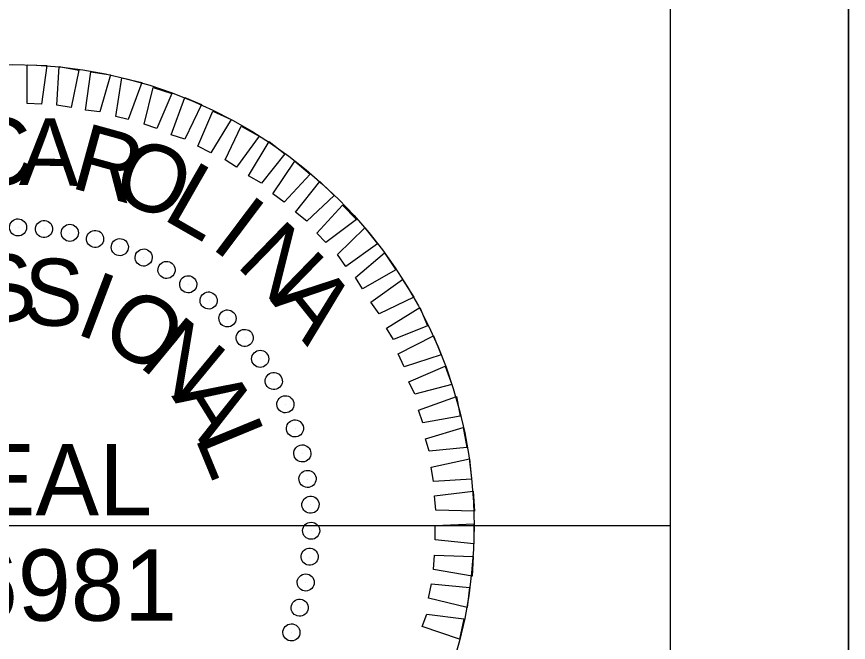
# Model space of a CAD drawing. Extents: x 1184121 to 1184397, y 1246506 to 1246661.
# Drawn here: x 1184351.43 to 1184360.32, y 1246631.37 to 1246638.07 of the extents above; entities that cross this region are included whole.
import ezdxf

# ---------------------------------------------------------------- set-up
doc = ezdxf.new("R2010")
doc.units = 0
for name, color, linetype in [('Scratch_Level_3', 7, 'Continuous'), ('Sheet PE Seal Cell', 7, 'Continuous'), ('Sheet Plan CELL', 7, 'Continuous'), ('Sheet Plot Border Outside CELL', 7, 'Continuous'), ('z - Construction', 7, 'Continuous')]:
    doc.layers.add(name, color=color, linetype=linetype)

msp = doc.modelspace()

# ---------------------------------------------------------------- linework, layer by layer
at = {"layer": 'Scratch_Level_3'}
msp.add_line((1184358.4219, 1246632.6201), (1184344.3472, 1246632.6204), dxfattribs=at)
msp.add_circle((1184351.3846, 1246632.6203), 4.9351, dxfattribs=at)
at = {"layer": 'Sheet PE Seal Cell'}
for p, q in [((1184351.4441, 1246635.8158), (1184351.4441, 1246635.8158)), ((1184351.724, 1246635.7967), (1184351.724, 1246635.7967)), ((1184351.9976, 1246635.7521), (1184351.9976, 1246635.7521)), ((1184352.2648, 1246635.6949), (1184352.2648, 1246635.6949)), ((1184352.532, 1246635.6058), (1184352.532, 1246635.6058)), ((1184352.7865, 1246635.4913), (1184352.7865, 1246635.4913)), ((1184353.0346, 1246635.3641), (1184353.0346, 1246635.3641)), ((1184353.2636, 1246635.205), (1184353.2636, 1246635.205)), ((1184353.4863, 1246635.0332), (1184353.4863, 1246635.0332)), ((1184353.6835, 1246634.8424), (1184353.6835, 1246634.8424)), ((1184353.8744, 1246634.6324), (1184353.8744, 1246634.6324)), ((1184354.0334, 1246634.4098), (1184354.0334, 1246634.4098)), ((1184354.1797, 1246634.168), (1184354.1797, 1246634.168)), ((1184354.307, 1246633.9199), (1184354.307, 1246633.9199)), ((1184354.4088, 1246633.6654), (1184354.4088, 1246633.6654)), ((1184354.4851, 1246633.3982), (1184354.4851, 1246633.3982)), ((1184354.536, 1246633.1183), (1184354.536, 1246633.1183)), ((1184354.5742, 1246632.8447), (1184354.5742, 1246632.8447)), ((1184354.5805, 1246632.5648), (1184354.5805, 1246632.5648)), ((1184354.5615, 1246632.2849), (1184354.5615, 1246632.2849)), ((1184354.5169, 1246632.0113), (1184354.5169, 1246632.0113)), ((1184354.4597, 1246631.7441), (1184354.4597, 1246631.7441)), ((1184354.3706, 1246631.4769), (1184354.3706, 1246631.4769))]:
    msp.add_line(p, q, dxfattribs=at)
for points in [[(1184351.5395, 1246637.1391), (1184351.5395, 1246637.5526), (1184351.7495, 1246637.5462), (1184351.6922, 1246637.1327)], [(1184351.8576, 1246637.12), (1184351.8831, 1246637.5335), (1184352.093, 1246637.4953), (1184352.0103, 1246637.0945)], [(1184352.163, 1246637.0691), (1184352.2202, 1246637.4762), (1184352.4302, 1246637.4444), (1184352.3157, 1246637.05)], [(1184352.4874, 1246636.9991), (1184352.5511, 1246637.4126), (1184352.7674, 1246637.3617), (1184352.621, 1246636.9673)], [(1184352.7928, 1246636.9164), (1184352.8883, 1246637.3108), (1184353.0855, 1246637.2472), (1184352.9264, 1246636.8719)], [(1184353.0791, 1246636.8019), (1184353.2254, 1246637.2027), (1184353.4036, 1246637.1263), (1184353.2254, 1246636.7573)], [(1184353.3654, 1246636.681), (1184353.5245, 1246637.0564), (1184353.7217, 1246636.9673), (1184353.5054, 1246636.611)], [(1184353.6581, 1246636.5347), (1184353.8298, 1246636.8973), (1184354.0207, 1246636.7891), (1184353.7789, 1246636.4583)], [(1184353.9062, 1246636.3629), (1184354.1288, 1246636.7319), (1184354.2943, 1246636.5983), (1184354.0461, 1246636.2866)], [(1184354.167, 1246636.172), (1184354.4024, 1246636.5219), (1184354.5678, 1246636.382), (1184354.2879, 1246636.083)], [(1184354.4088, 1246635.9748), (1184354.6696, 1246636.3056), (1184354.8223, 1246636.1529), (1184354.5296, 1246635.8794)], [(1184354.6378, 1246635.7521), (1184354.9114, 1246636.0512), (1184355.0641, 1246635.8985), (1184354.7332, 1246635.6504)], [(1184354.8605, 1246635.5231), (1184355.1531, 1246635.8094), (1184355.2867, 1246635.6376), (1184354.9495, 1246635.3959)], [(1184355.0513, 1246635.275), (1184355.3631, 1246635.5422), (1184355.4839, 1246635.3577), (1184355.1277, 1246635.1541)], [(1184355.2167, 1246635.0142), (1184355.5539, 1246635.2559), (1184355.6748, 1246635.065), (1184355.3058, 1246634.8869)], [(1184355.3822, 1246634.7342), (1184355.7384, 1246634.9569), (1184355.8211, 1246634.7597), (1184355.4585, 1246634.6133)], [(1184355.5094, 1246634.4607), (1184355.8848, 1246634.6515), (1184355.9675, 1246634.4479), (1184355.573, 1246634.3207)], [(1184355.6239, 1246634.1616), (1184356.012, 1246634.3271), (1184356.082, 1246634.1298), (1184355.6875, 1246634.028)], [(1184355.7257, 1246633.8563), (1184356.1329, 1246634.0026), (1184356.171, 1246633.7926), (1184355.7702, 1246633.7227)], [(1184355.802, 1246633.5509), (1184356.2029, 1246633.6718), (1184356.241, 1246633.4555), (1184355.8402, 1246633.4173)], [(1184355.8593, 1246633.2455), (1184356.2728, 1246633.3346), (1184356.2919, 1246633.1183), (1184355.8848, 1246633.0928)], [(1184355.8975, 1246632.9401), (1184356.311, 1246632.991), (1184356.3237, 1246632.7747), (1184355.9102, 1246632.7875)], [(1184355.9038, 1246632.622), (1184356.3174, 1246632.6411), (1184356.3174, 1246632.4248), (1184355.9038, 1246632.4694)], [(1184355.8975, 1246632.3039), (1184356.311, 1246632.2912), (1184356.2983, 1246632.0813), (1184355.8848, 1246632.1513)], [(1184355.8657, 1246631.9986), (1184356.2728, 1246631.9604), (1184356.2474, 1246631.7441), (1184355.8339, 1246631.8459)], [(1184355.8148, 1246631.6741), (1184356.2092, 1246631.6232), (1184356.1647, 1246631.4069), (1184355.7639, 1246631.5405)]]:
    msp.add_lwpolyline(points, close=True, dxfattribs=at)
for centre, major_axis in [((1184351.4425, 1246635.8127), (0.0016, 0.0916)), ((1184351.7204, 1246635.7957), (0.0096, 0.0911)), ((1184351.9957, 1246635.7546), (0.0175, 0.0899)), ((1184352.2664, 1246635.6896), (0.0253, 0.0881)), ((1184352.5304, 1246635.6013), (0.0328, 0.0855)), ((1184352.7857, 1246635.4903), (0.0402, 0.0823)), ((1184353.0304, 1246635.3574), (0.0472, 0.0785)), ((1184353.2625, 1246635.2038), (0.0538, 0.0741)), ((1184353.4804, 1246635.0305), (0.0601, 0.0691)), ((1184353.6824, 1246634.8388), (0.0659, 0.0636)), ((1184353.8668, 1246634.6303), (0.0712, 0.0577)), ((1184354.0324, 1246634.4065), (0.076, 0.0512)), ((1184354.1779, 1246634.1692), (0.0801, 0.0444)), ((1184354.3021, 1246633.92), (0.0837, 0.0373)), ((1184354.4041, 1246633.661), (0.0866, 0.0298)), ((1184354.4832, 1246633.3941), (0.0889, 0.0222)), ((1184354.5387, 1246633.1213), (0.0905, 0.0143)), ((1184354.5702, 1246632.8446), (0.0914, 0.0064)), ((1184354.5775, 1246632.5663), (0.0916, -0.0016)), ((1184354.5605, 1246632.2885), (0.0911, -0.0096)), ((1184354.5194, 1246632.0131), (0.0899, -0.0175)), ((1184354.4544, 1246631.7424), (0.0881, -0.0253)), ((1184354.366, 1246631.4784), (0.0855, -0.0328))]:
    msp.add_ellipse(centre, major_axis=major_axis, ratio=0.999708, dxfattribs=at)
at = {"layer": 'Sheet Plan CELL'}
msp.add_line((1184358.4193, 1246508.8745), (1184358.4228, 1246657.3636), dxfattribs=at)
at = {"layer": 'Sheet Plot Border Outside CELL'}
msp.add_lwpolyline([(1184121.0505, 1246660.5304), (1184360.3237, 1246660.5304), (1184360.3237, 1246505.7076), (1184121.0505, 1246505.7076)], close=True, dxfattribs=at)
at = {"layer": 'z - Construction'}
msp.add_line((1184360.3237, 1246505.7076), (1184360.3237, 1246660.5304), dxfattribs=at)

# ---------------------------------------------------------------- texts
at = {"layer": 'Sheet PE Seal Cell'}
for s, height, rotation, p in [('C', 0.7178, 6.21987, (1184350.9478, 1246636.2293)), ('A', 0.7173, 359.02032, (1184351.4504, 1246636.2675)), ('R', 0.7197, 344.6211, (1184351.9848, 1246636.242)), ('O', 0.7217, 337.42116, (1184352.4111, 1246636.1466)), ('L', 0.7237, 330.22088, (1184352.971, 1246635.9112)), ('I', 0.7249, 323.02014, (1184353.4863, 1246635.6058)), ('N', 0.7254, 315.81891, (1184353.7598, 1246635.4086)), ('S', 0.7179, 7.25561, (1184351.0305, 1246634.766)), ('S', 0.7174, 357.9004, (1184351.4886, 1246634.7724)), ('I', 0.7212, 339.1896, (1184352.0357, 1246634.6833)), ('A', 0.7249, 308.61715, (1184354.1352, 1246635.0332)), ('O', 0.7237, 329.83348, (1184352.2902, 1246634.5943)), ('N', 0.7253, 320.47661, (1184352.7165, 1246634.3398)), ('A', 0.7236, 301.76027, (1184353.0791, 1246634.009)), ('L', 0.7212, 292.40085, (1184353.3272, 1246633.57)), ('SEAL', 0.76321, 360, (1184350.2672, 1246632.73))]:
    msp.add_text(s, height=height, rotation=rotation, dxfattribs=at).set_placement(p)
msp.add_text('046981', height=0.76321, dxfattribs=at).set_placement((1184349.7364, 1246631.6031))

doc.saveas('drawing.dxf')
